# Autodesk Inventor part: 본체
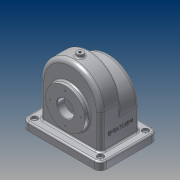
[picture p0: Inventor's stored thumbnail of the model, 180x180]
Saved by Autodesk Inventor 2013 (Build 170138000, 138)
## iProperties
Created: 2017-11
Part Number: 본체
Material: 알루미늄 6061
Document SubType Name: Modeling
Designer: Administrator
Density: 2.71 g/cm^3
Mass: 1079.49 g
Surface Area: 1182.07 cm^2
Volume: 398.335 cm^3
Author: Administrator
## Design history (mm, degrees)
sketch "스케치1"
  geometry: L1 (-58, -57)-(58, -57); L2 (58, -57)-(58, 23); L3 (-58, -57)-(-58, 23); A1 r 58 centre (0, 0) between (58, 0) and (-58, 0); A2 r 58 centre (0, 23) between (58, 23) and (-58, 23); 1 further point
  constraints: 6 end point, 4 point on circle, 2 centre point, 2 point on line, 2 tangent, 1 coincident, 1 horizontal, 1 parallel, 1 perpendicular, 1 vertical alignment
  dimensions: "d2" = 58 radius of A1; "d3" = 116 diameter of A2; "d4" = 80 distance from line of L1 A2.centre; "d6" = 57 distance from line of L1 point (0, 0)
extrude "돌출1" new body sketch "스케치1" distance "d7" = 38; taper "d8" = 0 deg
extrude "돌출2" join sketch "스케치1" distance "d9" = 38; taper "d10" = 0 deg
feature "쉘1" dims "d11" = 5
sketch "스케치2"
  geometry: L1 (-58, -57)-(58, -57) reference; C1 r 16 at (0, 8); C2 r 31 at (0, 8); A1 r 58 centre (0, 0) between (58, 0) and (-58, 0) reference
  constraints: 2 centre point, 1 coincident, 1 vertical alignment
  dimensions: "d12" = 32 diameter of C1; "d13" = 62 diameter of C2; "d14" = 65 distance from line of L1 C1.centre
extrude "돌출3" cut sketch "스케치2" stored distance "d15" = 38; taper "d16" = 0 deg
extrude "돌출4" join sketch "스케치2" distance "d17" = 10; taper "d18" = 0 deg
sketch "스케치3"
  geometry: L1 (116, 0)-(116, -76) reference; L2 (0, 0)-(116, 0) reference; L3 (0, -76)-(0, 0) reference; L4 (116, -76)-(0, -76) reference; L5 (-5, -93)-(121, -93); L6 (133, -81)-(133, 5); L7 (121, 17)-(-5, 17); L8 (-17, 5)-(-17, -81); L9 (-17, -93)-(133, 17); L10 (133, -93)-(-17, 17); A1 r 12 centre (-5, 5) between (-5, 17) and (-17, 5); A2 r 12 centre (121, 5) between (133, 5) and (121, 17); A3 r 12 centre (121, -81) between (121, -93) and (133, -81); A4 r 12 centre (-5, -81) between (-17, -81) and (-5, -93); 3 further points
  constraints: 12 end point, 8 point on circle, 8 point on line, 8 tangent, 4 centre point, 3 equal radius, 3 midpoint, 2 parallel, 1 coincident, 1 horizontal, 1 perpendicular
  dimensions: "d19" = 150 distance of L9.end L10.end; "d21" = 110 distance of L10.start L9.end; "d22" = 12 radius of A1
extrude "돌출5" join sketch "스케치3" distance "d23" = 15; taper "d24" = 0 deg
sketch "스케치4"
  geometry: C1 r 16 at (0, 8) reference; C2 r 37.5 at (0, 8); 1 further point
  constraints: 1 centre point, 1 coincident
  dimensions: "d25" = 75 diameter of C2
extrude "돌출6" join sketch "스케치4" distance "d27" = 9; taper "d28" = 0 deg
sketch "스케치5"
  geometry: A1 r 12 centre (121, -5) between (121, -17) and (133, -5) reference; A2 r 12 centre (121, 81) between (133, 81) and (121, 93) reference; A3 r 12 centre (-5, 81) between (-5, 93) and (-17, 81) reference; A4 r 12 centre (-5, -5) between (-17, -5) and (-5, -17) reference; 1 further point
hole "구멍1" sketch "스케치5" at (-5, -5), (121, -5), (121, 81), (-5, 81) diameter "d29" = 5; stored, may be unused: countersink angle "d33" = 90 deg, drill point angle "d35" = 118 deg; dims "d30" = 6, "d31" = 12, "d32" = 5, "d34" = 8
node "작업 평면1"
sketch "스케치6"
  geometry: L1 (75, -43)-(75, 43) reference; L2 (58, 38)-(-58, 38) reference; C1 r 6 at (0, 19); 1 further point
  constraints: 1 centre point
  dimensions: "d37" = 75 distance from line of C1.centre L1; "d38" = 19 distance from line of C1.centre L2; "d39" = 12 diameter of C1
extrude "돌출7" join sketch "스케치6" stored distance "d40" = 9; taper "d41" = 0 deg
hole "구멍2" diameter "d44" = 4.459; stored, may be unused: countersink angle "d48" = 90 deg, drill point angle "d50" = 0 deg; dims "d42" = 10, "d43" = 10, "d45" = 6, "d46" = 12, "d47" = 5, "d49" = 8
sketch "스케치7"
  geometry: C1 r 16 at (0, 0) reference; 2 further points
  constraints: 1 vertical alignment
  dimensions: "d51" = 29 distance of C1.centre point (0, 29)
sketch "스케치8"
  geometry: C1 r 16 at (0, 0) reference; 2 further points
  constraints: 1 vertical alignment
  dimensions: "d52" = 26 distance of C1.centre point (0, 26)
hole "구멍3" sketch "스케치7" diameter "d53" = 2.459; stored, may be unused: countersink angle "d57" = 90 deg, drill point angle "d59" = 118 deg; dims "d54" = 6, "d55" = 12, "d56" = 5, "d58" = 8
hole "구멍4" sketch "스케치8" diameter "d60" = 2.459; stored, may be unused: countersink angle "d64" = 90 deg, drill point angle "d66" = 118 deg; dims "d61" = 6, "d62" = 12, "d63" = 5, "d65" = 8
fillet "모깎기2" dims "d71" = 8
fillet "모깎기1" dims "d70" = 3
chamfer "모따기1" distance "d72" = 1; stored, may be unused: second distance "d73" = 2, angle "d74" = 45 deg
sketch "스케치9"
  geometry: L1 (-8, 65)-(-8, 0) reference; L2 (-13, -15)-(73, -15) reference; 2 further points
  constraints: 1 other
  dimensions: "d75" = 38 distance from line of point (30, 25) L1; "d76" = 40 distance from line of L2 point (30, 25)
feature "엠보싱1" sketch "스케치9" dims "d77" = 0.5, "d78" = 0
node "솔리드1"
pattern_circular "원형 패턴1" dims angle "d68" = 360 deg
other parameters: "d36" = 87
